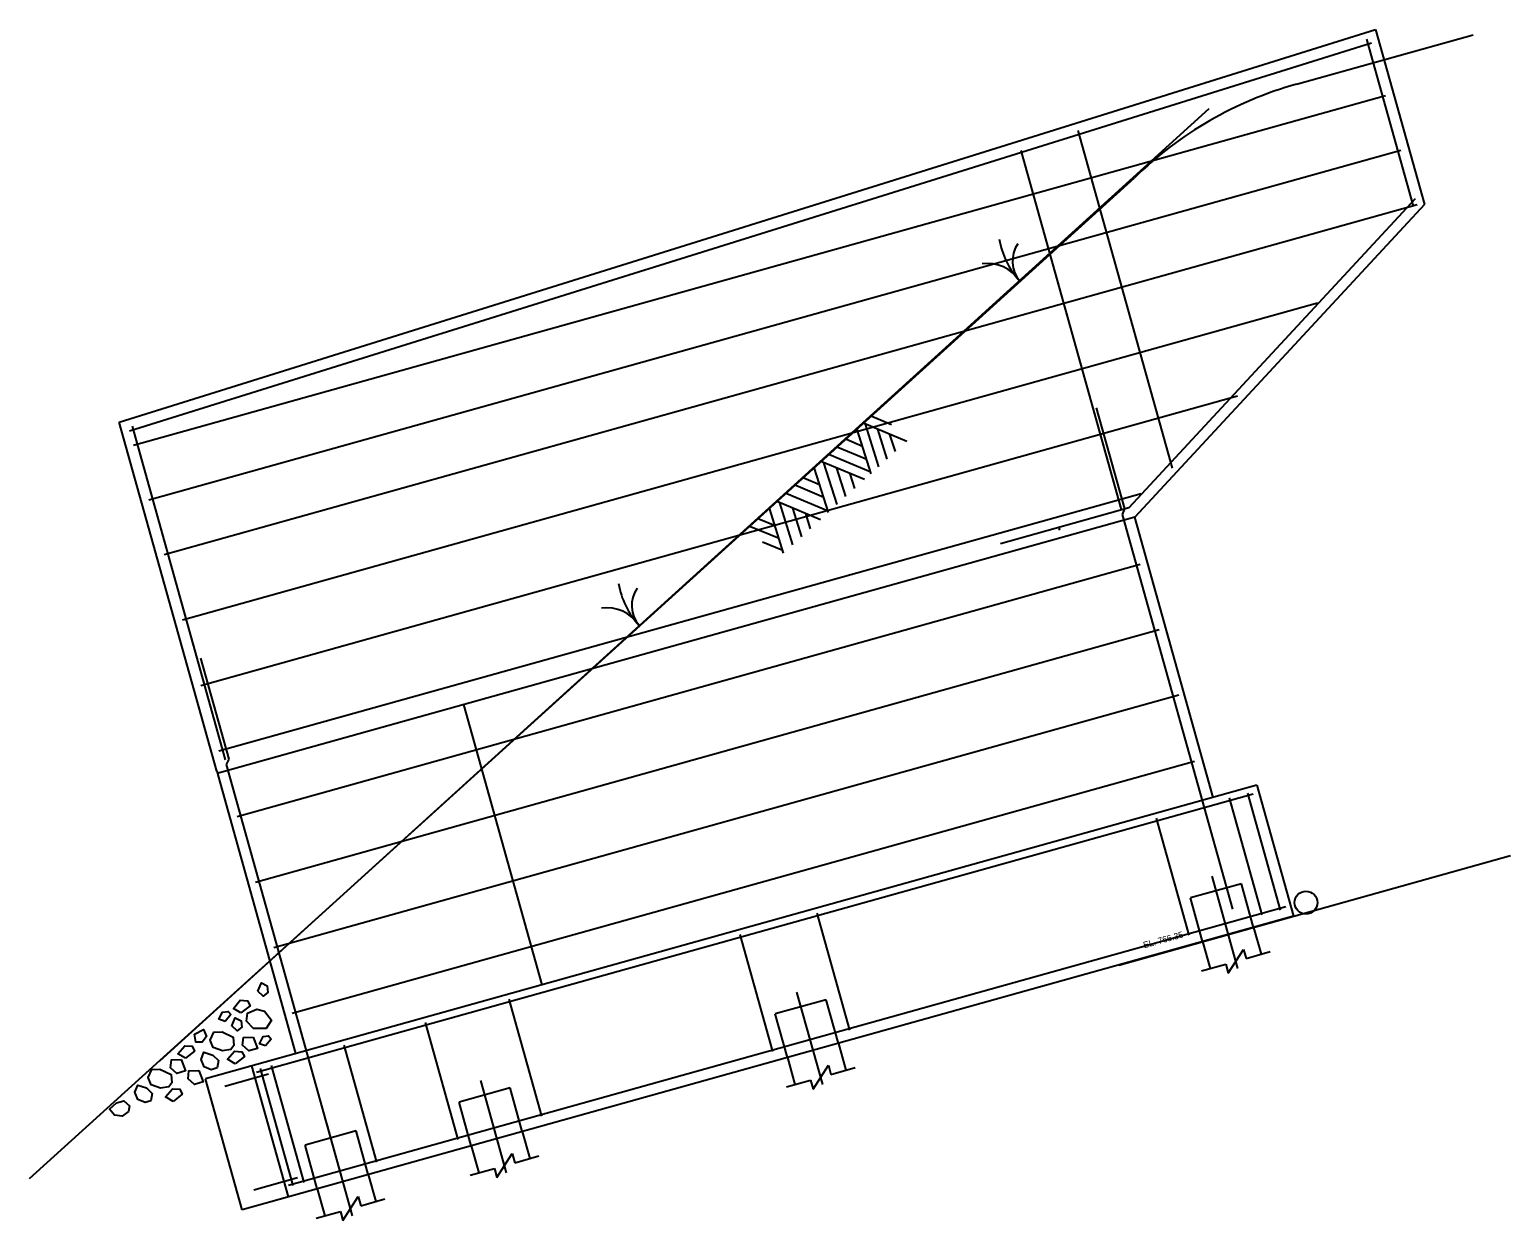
# Model space of a CAD drawing. Extents: x 1539537 to 1543620, y 586918 to 587494.
# Drawn here: x 1543287.27 to 1543319.91, y 587315.22 to 587341.48 of the extents above; entities that cross this region are included whole.
import ezdxf

# ---------------------------------------------------------------- set-up
doc = ezdxf.new("R2010")
doc.units = 0
for name, color, linetype in [('BR_P_Gen_Ground_Slope', 7, 'Continuous'), ('BR_P_Gen_Text', 7, 'Continuous'), ('BR_P_Sub_Const_Joint', 7, 'Continuous'), ('BR_P_Sub_Deep_Centerline', 7, 'Continuous'), ('BR_P_Sub_Deep_Hidden', 7, 'Continuous'), ('BR_P_Sub_Deep_Object', 7, 'Continuous'), ('BR_P_Sub_Foot_Object', 7, 'Continuous'), ('BR_P_Sub_Hidden', 7, 'Continuous'), ('BR_P_Sub_Object', 7, 'Continuous'), ('BR_P_Sub_Reinforcing', 7, 'Continuous'), ('RD_P_Text', 7, 'Continuous'), ('SC_Shading1', 7, 'Continuous')]:
    doc.layers.add(name, color=color, linetype=linetype)

msp = doc.modelspace()

# ---------------------------------------------------------------- linework, layer by layer
at = {"layer": 'BR_P_Gen_Ground_Slope'}
for p, q in [((1543315.196, 587340.276), (1543319.085, 587341.363)), ((1543290.14, 587318.739), (1543313.269, 587339.738)), ((1543287.27, 587316.151), (1543311.62, 587338.211)), ((1543311.277, 587320.855), (1543319.908, 587323.267))]:
    msp.add_line(p, q, dxfattribs=at)
for centre, radius, start, end in [((1543317.423, 587332.291), 8.29, 105.5836, 134.4301), ((1543310.436, 587337.161), 1.818, 189.5596, 222.441), ((1543309.611, 587336.373), 0.677, 145.6033, 220.3926), ((1543308.378, 587335.473), 0.852, 32.7203, 97.5152), ((1543302.044, 587329.568), 1.818, 189.5596, 222.441), ((1543301.218, 587328.78), 0.677, 145.6033, 220.3926), ((1543299.985, 587327.881), 0.852, 32.7203, 97.5152)]:
    msp.add_arc(centre, radius, start, end, dxfattribs=at)
at = {"layer": 'BR_P_Gen_Text'}
for p, q in [((1543313.689, 587320.677), (1543314.027, 587321.2)), ((1543314.027, 587321.2), (1543314.082, 587321.001)), ((1543314.082, 587321.001), (1543314.617, 587321.15)), ((1543313.1, 587320.727), (1543313.634, 587320.876)), ((1543313.634, 587320.876), (1543313.689, 587320.677)), ((1543304.54, 587318.12), (1543304.877, 587318.644)), ((1543304.877, 587318.644), (1543304.933, 587318.445)), ((1543304.933, 587318.445), (1543305.467, 587318.594)), ((1543303.95, 587318.17), (1543304.484, 587318.319)), ((1543304.484, 587318.319), (1543304.54, 587318.12)), ((1543297.57, 587316.173), (1543297.907, 587316.696)), ((1543297.907, 587316.696), (1543297.963, 587316.497)), ((1543297.963, 587316.497), (1543298.497, 587316.646)), ((1543296.98, 587316.223), (1543297.515, 587316.372)), ((1543297.515, 587316.372), (1543297.57, 587316.173)), ((1543294.176, 587315.225), (1543294.514, 587315.748)), ((1543294.514, 587315.748), (1543294.569, 587315.549)), ((1543294.569, 587315.549), (1543295.103, 587315.698)), ((1543293.586, 587315.274), (1543294.121, 587315.424)), ((1543294.121, 587315.424), (1543294.176, 587315.225))]:
    msp.add_line(p, q, dxfattribs=at)
msp.add_arc((1543309.929, 587330.539), 0.0833, 285.6111, 316.9858, dxfattribs=at)
at = {"layer": 'BR_P_Sub_Const_Joint'}
msp.add_line((1543311.633, 587330.732), (1543291.407, 587325.08), dxfattribs=at)
at = {"layer": 'BR_P_Sub_Deep_Centerline'}
for p, q in [((1543313.326, 587322.813), (1543313.896, 587320.775)), ((1543304.176, 587320.257), (1543304.746, 587318.218)), ((1543297.207, 587318.309), (1543297.776, 587316.271)), ((1543293.813, 587317.361), (1543294.382, 587315.322))]:
    msp.add_line(p, q, dxfattribs=at)
at = {"layer": 'BR_P_Sub_Deep_Hidden'}
for p, q in [((1543313.978, 587322.648), (1543312.854, 587322.334)), ((1543314.247, 587321.685), (1543313.978, 587322.648)), ((1543313.123, 587321.371), (1543312.854, 587322.334)), ((1543304.828, 587320.091), (1543303.705, 587319.778)), ((1543305.097, 587319.128), (1543304.828, 587320.091)), ((1543303.974, 587318.814), (1543303.705, 587319.778)), ((1543297.859, 587318.144), (1543296.735, 587317.83)), ((1543298.128, 587317.181), (1543297.859, 587318.144)), ((1543297.004, 587316.867), (1543296.735, 587317.83)), ((1543294.465, 587317.196), (1543293.341, 587316.882)), ((1543293.61, 587315.919), (1543293.341, 587316.882)), ((1543294.734, 587316.233), (1543294.465, 587317.196))]:
    msp.add_line(p, q, dxfattribs=at)
at = {"layer": 'BR_P_Sub_Deep_Object'}
for p, q in [((1543314.247, 587321.685), (1543314.412, 587321.093)), ((1543313.123, 587321.371), (1543313.289, 587320.779)), ((1543305.097, 587319.128), (1543305.263, 587318.537)), ((1543303.974, 587318.814), (1543304.139, 587318.223)), ((1543298.128, 587317.181), (1543298.293, 587316.589)), ((1543297.004, 587316.867), (1543297.169, 587316.275)), ((1543294.734, 587316.233), (1543294.899, 587315.641)), ((1543293.61, 587315.919), (1543293.775, 587315.327))]:
    msp.add_line(p, q, dxfattribs=at)
msp.add_circle((1543315.403, 587322.231), 0.25, dxfattribs=at)
at = {"layer": 'BR_P_Sub_Foot_Object'}
for p, q in [((1543314.323, 587324.821), (1543291.145, 587318.345)), ((1543314.323, 587324.821), (1543315.13, 587321.932)), ((1543315.13, 587321.932), (1543291.952, 587315.455)), ((1543292.978, 587315.742), (1543292.171, 587318.631)), ((1543291.952, 587315.455), (1543291.145, 587318.345))]:
    msp.add_line(p, q, dxfattribs=at)
at = {"layer": 'BR_P_Sub_Hidden'}
msp.add_line((1543296.831, 587326.596), (1543298.557, 587320.416), dxfattribs=at)
at = {"layer": 'BR_P_Sub_Object'}
for p, q in [((1543289.244, 587332.821), (1543316.936, 587341.48)), ((1543316.936, 587341.48), (1543318.012, 587337.627)), ((1543318.012, 587337.627), (1543311.633, 587330.732)), ((1543291.394, 587325.126), (1543289.244, 587332.821)), ((1543313.359, 587324.552), (1543311.633, 587330.732)), ((1543291.394, 587325.126), (1543293.134, 587318.901))]:
    msp.add_line(p, q, dxfattribs=at)
at = {"layer": 'BR_P_Sub_Reinforcing'}
for p, q in [((1543289.471, 587332.63), (1543316.844, 587341.189)), ((1543316.735, 587341.27), (1543317.765, 587337.585)), ((1543317.156, 587340.02), (1543289.561, 587332.309)), ((1543310.376, 587339.254), (1543312.456, 587331.811)), ((1543317.49, 587338.815), (1543289.897, 587331.105)), ((1543309.115, 587338.812), (1543311.327, 587330.897)), ((1543309.115, 587338.812), (1543311.173, 587331.45)), ((1543317.853, 587337.619), (1543290.233, 587329.901)), ((1543317.806, 587337.746), (1543311.497, 587330.933)), ((1543315.655, 587335.447), (1543290.637, 587328.457)), ((1543313.892, 587333.397), (1543291.041, 587327.012)), ((1543311.409, 587330.913), (1543310.787, 587333.141)), ((1543289.528, 587332.735), (1543291.583, 587325.38)), ((1543311.768, 587331.246), (1543291.444, 587325.567)), ((1543311.497, 587330.933), (1543308.67, 587330.143)), ((1543311.357, 587330.791), (1543311.409, 587330.913)), ((1543313.789, 587322.087), (1543311.357, 587330.791)), ((1543311.75, 587329.684), (1543291.848, 587324.123)), ((1543312.168, 587328.243), (1543292.252, 587322.678)), ((1543291.665, 587325.396), (1543291.043, 587327.624)), ((1543312.601, 587326.807), (1543292.655, 587321.233)), ((1543291.613, 587325.274), (1543291.665, 587325.396)), ((1543294.045, 587316.57), (1543291.613, 587325.274)), ((1543312.946, 587325.346), (1543293.059, 587319.789)), ((1543314.241, 587324.625), (1543292.27, 587318.486)), ((1543313.709, 587324.538), (1543314.43, 587321.96)), ((1543314.113, 587324.641), (1543314.833, 587322.063)), ((1543312.104, 587324.09), (1543312.824, 587321.512)), ((1543292.974, 587316), (1543314.958, 587322.143)), ((1543304.625, 587322), (1543305.345, 587319.422)), ((1543302.925, 587321.525), (1543303.645, 587318.947)), ((1543297.835, 587320.103), (1543298.555, 587317.525)), ((1543295.985, 587319.586), (1543296.705, 587317.008)), ((1543294.196, 587319.086), (1543294.916, 587316.508)), ((1543292.349, 587318.57), (1543293.069, 587315.992)), ((1543292.591, 587318.637), (1543293.311, 587316.06)), ((1543291.571, 587318.185), (1543292.539, 587318.455)), ((1543292.209, 587315.9), (1543293.177, 587316.171))]:
    msp.add_line(p, q, dxfattribs=at)
at = {"layer": 'SC_Shading1'}
for p, q in [((1543306.27, 587332.766), (1543305.835, 587332.951)), ((1543305.817, 587331.688), (1543305.511, 587332.66)), ((1543306.602, 587332.401), (1543305.665, 587332.797)), ((1543305.987, 587331.842), (1543305.691, 587332.781)), ((1543306.173, 587332.012), (1543305.963, 587332.669)), ((1543306.354, 587332.175), (1543306.232, 587332.556)), ((1543305.72, 587331.999), (1543305.084, 587332.269)), ((1543305.629, 587332.291), (1543305.275, 587332.442)), ((1543305.673, 587331.557), (1543304.732, 587331.949)), ((1543305.066, 587331.006), (1543304.778, 587331.928)), ((1543305.808, 587331.719), (1543304.9, 587332.101)), ((1543304.682, 587331.442), (1543304.338, 587331.59)), ((1543304.878, 587330.834), (1543304.573, 587331.804)), ((1543305.262, 587331.183), (1543305.062, 587331.811)), ((1543305.461, 587331.364), (1543305.357, 587331.688)), ((1543304.869, 587330.861), (1543303.958, 587331.246)), ((1543304.774, 587331.162), (1543304.156, 587331.425)), ((1543304.7, 587330.673), (1543303.761, 587331.066)), ((1543304.093, 587330.122), (1543303.805, 587331.048)), ((1543304.288, 587330.299), (1543304.091, 587330.929)), ((1543303.701, 587330.536), (1543303.346, 587330.689)), ((1543303.89, 587329.937), (1543303.585, 587330.906)), ((1543304.481, 587330.474), (1543304.376, 587330.808)), ((1543303.789, 587330.256), (1543303.159, 587330.519)), ((1543303.87, 587329.996), (1543303.427, 587330.182))]:
    msp.add_line(p, q, dxfattribs=at)
for points in [[(1543292.3, 587320.278), (1543292.378, 587320.46), (1543292.509, 587320.394), (1543292.519, 587320.251), (1543292.418, 587320.169), (1543292.3, 587320.278)], [(1543291.579, 587319.612), (1543291.441, 587319.658), (1543291.523, 587319.814), (1543291.645, 587319.831), (1543291.702, 587319.761), (1543291.579, 587319.612)], [(1543291.928, 587319.801), (1543291.762, 587319.9), (1543291.911, 587320.079), (1543292.076, 587320.067), (1543292.13, 587319.959), (1543291.928, 587319.801)], [(1543292.451, 587319.837), (1543292.6, 587319.642), (1543292.482, 587319.452), (1543292.202, 587319.454), (1543292.051, 587319.616), (1543292.069, 587319.79), (1543292.281, 587319.879), (1543292.451, 587319.837)], [(1543291.726, 587319.511), (1543291.804, 587319.693), (1543291.935, 587319.626), (1543291.945, 587319.484), (1543291.844, 587319.402), (1543291.726, 587319.511)], [(1543290.908, 587319.328), (1543291.103, 587319.43), (1543291.169, 587319.281), (1543291.077, 587319.152), (1543290.933, 587319.152), (1543290.908, 587319.328)], [(1543291.512, 587319.383), (1543291.757, 587319.267), (1543291.771, 587319.082), (1543291.708, 587318.994), (1543291.525, 587318.965), (1543291.319, 587319.04), (1543291.253, 587319.201), (1543291.334, 587319.378), (1543291.512, 587319.383)], [(1543292.194, 587319.264), (1543292.29, 587319.018), (1543292.103, 587318.96), (1543291.961, 587319.086), (1543291.981, 587319.258), (1543292.194, 587319.264)], [(1543292.472, 587319.075), (1543292.334, 587319.121), (1543292.415, 587319.277), (1543292.538, 587319.294), (1543292.594, 587319.224), (1543292.472, 587319.075)], [(1543290.705, 587318.799), (1543290.539, 587318.898), (1543290.689, 587319.077), (1543290.853, 587319.065), (1543290.907, 587318.957), (1543290.705, 587318.799)], [(1543291.309, 587318.87), (1543291.43, 587318.749), (1543291.401, 587318.589), (1543291.275, 587318.545), (1543291.117, 587318.613), (1543291.052, 587318.774), (1543291.112, 587318.931), (1543291.309, 587318.87)], [(1543291.801, 587318.677), (1543291.635, 587318.776), (1543291.785, 587318.955), (1543291.949, 587318.943), (1543292.003, 587318.835), (1543291.801, 587318.677)], [(1543290.143, 587318.556), (1543290.388, 587318.44), (1543290.402, 587318.255), (1543290.338, 587318.167), (1543290.156, 587318.137), (1543289.95, 587318.213), (1543289.884, 587318.374), (1543289.965, 587318.55), (1543290.143, 587318.556)], [(1543290.607, 587318.769), (1543290.703, 587318.523), (1543290.516, 587318.465), (1543290.375, 587318.591), (1543290.394, 587318.763), (1543290.607, 587318.769)], [(1543290.997, 587318.527), (1543291.093, 587318.281), (1543290.906, 587318.223), (1543290.764, 587318.349), (1543290.783, 587318.521), (1543290.997, 587318.527)], [(1543289.849, 587318.145), (1543289.97, 587318.025), (1543289.941, 587317.864), (1543289.816, 587317.821), (1543289.657, 587317.888), (1543289.592, 587318.049), (1543289.652, 587318.207), (1543289.849, 587318.145)], [(1543290.432, 587317.849), (1543290.266, 587317.949), (1543290.416, 587318.128), (1543290.58, 587318.116), (1543290.634, 587318.008), (1543290.432, 587317.849)], [(1543289.184, 587317.816), (1543289.349, 587317.859), (1543289.473, 587317.754), (1543289.448, 587317.623), (1543289.309, 587317.52), (1543289.138, 587317.545), (1543289.032, 587317.677), (1543289.184, 587317.816)]]:
    msp.add_lwpolyline(points, dxfattribs=at)

# ---------------------------------------------------------------- texts
at = {"layer": 'RD_P_Text'}
msp.add_text('EL. 766.35', height=0.14, rotation=15.6111, dxfattribs=at).set_placement((1543311.838, 587321.223))

doc.saveas('drawing.dxf')
